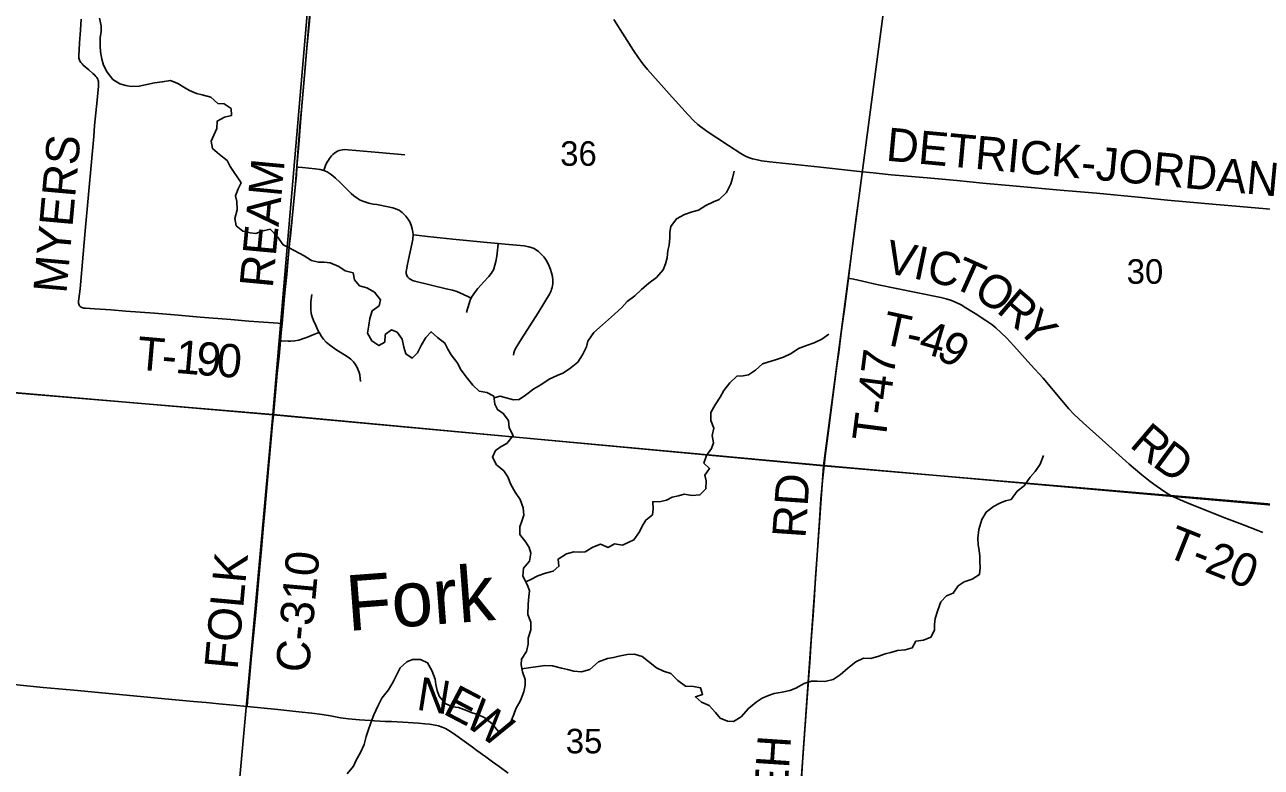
# Model space of a CAD drawing. Extents: x 0 to 1134, y 0 to 440.
# Drawn here: x 840.522 to 842.63, y 363.897 to 365.164 of the extents above; entities that cross this region are included whole.
import ezdxf

# ---------------------------------------------------------------- set-up
doc = ezdxf.new("R2010")
doc.units = 0
for name, color, linetype in [('GM_X_County_Road', 7, 'Continuous'), ('GM_X_County_Road_Text', 7, 'Continuous'), ('GM_X_Minor_River', 7, 'Continuous'), ('GM_X_Minor_River_Text', 7, 'Continuous'), ('GM_X_Section', 7, 'Continuous'), ('GM_X_Section_Text', 7, 'Continuous'), ('GM_X_Township', 7, 'Continuous'), ('GM_X_Township_Road', 7, 'Continuous'), ('GM_X_Township_Road_Text', 7, 'Continuous'), ('GM_X_Unincorporated', 7, 'Continuous')]:
    doc.layers.add(name, color=color, linetype=linetype)

msp = doc.modelspace()

# ---------------------------------------------------------------- linework, layer by layer
at = {"layer": 'GM_X_County_Road'}
for points in [[(840.9857, 364.9213), (840.9888, 364.9598), (840.9916, 364.9969), (840.9935, 365.0186), (840.9986, 365.0774), (841.0027, 365.1238), (841.0058, 365.1578), (841.0091, 365.1949), (841.0128, 365.2351), (841.0161, 365.2723), (841.0182, 365.297), (841.0212, 365.331), (841.0237, 365.3589), (841.026, 365.3867), (841.0292, 365.4207), (841.0319, 365.4485), (841.034, 365.4702), (841.0367, 365.5011), (841.0372, 365.5064)], [(841.5258, 365.1725), (841.5592, 365.1201), (841.5679, 365.1072), (841.5754, 365.0973), (841.5834, 365.0877), (841.6205, 365.0458), (841.6525, 365.01), (841.6622, 365.0001), (841.6693, 364.9936), (841.6742, 364.9896), (841.6869, 364.9806), (841.7013, 364.9711), (841.7213, 364.9578), (841.7425, 364.9442), (841.7491, 364.9404), (841.7557, 364.9375), (841.7621, 364.9351), (841.7706, 364.9331), (841.7774, 364.9317), (841.792, 364.9298), (841.8785, 364.9206), (841.9497, 364.9129)], [(840.9662, 364.7171), (840.9683, 364.7376), (840.9708, 364.7654), (840.9732, 364.7901), (840.975, 364.8086), (840.9775, 364.8333), (840.9833, 364.8919), (840.9846, 364.9073), (840.9857, 364.9213)], [(841.9497, 364.9129), (841.9681, 364.9109), (841.999, 364.908), (842.0268, 364.9053), (842.0733, 364.9014), (842.1104, 364.8982), (842.155, 364.8938), (842.2125, 364.8887), (842.2867, 364.8818), (842.3145, 364.8794), (842.3486, 364.8763), (842.4197, 364.8695), (842.4701, 364.8648), (842.5527, 364.8574), (842.5929, 364.8537), (842.6517, 364.8485), (842.7074, 364.8436), (842.7415, 364.8407), (842.7972, 364.8355), (842.8652, 364.8294), (842.9053, 364.8257), (842.9385, 364.8227)], [(840.9602, 364.6544), (840.9646, 364.7005), (840.9662, 364.7171)], [(840.9575, 364.6247), (840.9588, 364.6387), (840.9602, 364.6544)], [(840.9454, 364.4979), (840.9522, 364.5688), (840.9552, 364.5985), (840.9575, 364.6247)], [(840.9009, 364.0006), (840.9019, 364.0164), (840.9083, 364.0875), (840.9147, 364.1554), (840.917, 364.1802), (840.9201, 364.2141), (840.9256, 364.2759), (840.9282, 364.3038), (840.931, 364.3347), (840.9356, 364.3872), (840.9441, 364.483), (840.9454, 364.4979)], [(840.0509, 364.0808), (840.0706, 364.0789), (840.1015, 364.076), (840.151, 364.0715), (840.1912, 364.0679), (840.2129, 364.0661), (840.2315, 364.0647), (840.2963, 364.0592), (840.3117, 364.0578), (840.3302, 364.0559), (840.358, 364.0526), (840.392, 364.0492), (840.4259, 364.0456), (840.4507, 364.0431), (840.4971, 364.0386), (840.5527, 364.0332), (840.6053, 364.0283), (840.7785, 364.0122), (840.8094, 364.0093), (840.8311, 364.0073), (840.8527, 364.0053), (840.8777, 364.0029), (840.9009, 364.0006)], [(840.9009, 364.0006), (840.9528, 363.9953), (840.9886, 363.9918), (841.0108, 363.9893), (841.0284, 363.9868), (841.0429, 363.9845), (841.0599, 363.9816), (841.0738, 363.9798), (841.0921, 363.9779), (841.1016, 363.9771), (841.1112, 363.9765), (841.1176, 363.9761), (841.1358, 363.9753), (841.1468, 363.9748), (841.1662, 363.9739), (841.1926, 363.9722), (841.2036, 363.9713), (841.2118, 363.9703), (841.2211, 363.9689), (841.2272, 363.9675), (841.2332, 363.9655), (841.2389, 363.963), (841.2444, 363.96), (841.2523, 363.9548), (841.2748, 363.9385), (841.2848, 363.9312), (841.2924, 363.9258), (841.3075, 363.9147), (841.3192, 363.9062), (841.3302, 363.8982), (841.3458, 363.8868)]]:
    msp.add_lwpolyline(points, dxfattribs=at)
at = {"layer": 'GM_X_Minor_River'}
for points in [[(841.1046, 364.715), (841.0925, 364.7186), (841.0835, 364.7289), (841.0814, 364.7407), (841.0681, 364.7439), (841.0572, 364.7513), (841.0425, 364.7575), (841.0319, 364.7588), (841.0224, 364.7589), (841.0106, 364.7617), (840.9982, 364.7698), (840.9725, 364.7831), (840.9623, 364.7885), (840.9526, 364.8019), (840.9399, 364.815), (840.9258, 364.8114), (840.9155, 364.8077), (840.906, 364.8086), (840.8935, 364.8118), (840.8822, 364.821), (840.8797, 364.8332), (840.8837, 364.8483), (840.8831, 364.8624), (840.8806, 364.8719), (840.8857, 364.8836), (840.8904, 364.8942), (840.8717, 364.9218), (840.8665, 364.9321), (840.8537, 364.9425), (840.8417, 364.9526), (840.8396, 364.9651), (840.8439, 364.9753), (840.849, 364.9867), (840.8499, 364.9996), (840.8621, 365.0063), (840.8739, 365.0088), (840.8737, 365.0209), (840.8613, 365.0287), (840.851, 365.0296), (840.8386, 365.04), (840.8239, 365.0443), (840.8144, 365.0463), (840.8027, 365.0518), (840.7929, 365.0576), (840.7827, 365.0634), (840.7702, 365.0689), (840.7561, 365.0664), (840.7428, 365.065), (840.7295, 365.0618), (840.7165, 365.0593), (840.7032, 365.0587), (840.6938, 365.0599), (840.6839, 365.0631), (840.6715, 365.0705), (840.6621, 365.0827), (840.6558, 365.095), (840.6529, 365.1053), (840.6508, 365.1178), (840.6502, 365.1273), (840.6503, 365.1418), (840.6516, 365.152), (840.6521, 365.1622), (840.6492, 365.1748)], [(841.3218, 364.5271), (841.3321, 364.5303), (841.3423, 364.5271), (841.3548, 364.5236), (841.3643, 364.5246), (841.3755, 364.5321), (841.3893, 364.5429), (841.4015, 364.5492), (841.4157, 364.559), (841.4291, 364.5656), (841.439, 364.5693), (841.4501, 364.5768), (841.4643, 364.588), (841.4724, 364.6008), (841.4794, 364.6144), (841.4814, 364.6239), (841.4919, 364.6386), (841.5065, 364.6517), (841.5169, 364.6611), (841.5272, 364.6701), (841.5395, 364.6817), (841.5488, 364.6915), (841.5618, 364.7012), (841.5733, 364.7121), (841.5856, 364.723), (841.5987, 364.7327), (841.6098, 364.7459), (841.6138, 364.7557), (841.6166, 364.7663), (841.6182, 364.7785), (841.6202, 364.7879), (841.6212, 364.8005), (841.6213, 364.81), (841.6229, 364.8198), (841.6326, 364.8326), (841.6463, 364.84), (841.6593, 364.8445), (841.67, 364.8477), (841.6826, 364.8552), (841.6956, 364.8615), (841.7056, 364.8659), (841.7179, 364.8776), (841.7253, 364.8923), (841.7284, 364.9021), (841.7312, 364.9143)], [(841.1564, 364.0566), (841.1618, 364.0664), (841.173, 364.0766), (841.1829, 364.0806), (841.1962, 364.0808), (841.2083, 364.0754), (841.2157, 364.062), (841.2212, 364.0475), (841.2226, 364.038), (841.2248, 364.0281), (841.2281, 364.0185), (841.2382, 364.0058), (841.251, 364), (841.2612, 363.9991), (841.2745, 363.9936), (841.2843, 363.9901), (841.2941, 363.9869), (841.3062, 363.9815), (841.3186, 363.9711), (841.3287, 363.9584), (841.3413, 363.9621), (841.3498, 363.9734), (841.3553, 363.987), (841.3588, 363.9968), (841.367, 364.0108), (841.3725, 364.0255), (841.3745, 364.0369), (841.3747, 364.0468), (841.3703, 364.0598), (841.3678, 364.072), (841.3686, 364.0814), (841.3772, 364.0946), (841.38, 364.1072), (841.3801, 364.117), (841.3845, 364.1314), (841.3843, 364.1447), (841.3795, 364.1577), (841.3797, 364.1752), (841.381, 364.1885), (841.3819, 364.198), (841.3786, 364.2079), (841.3708, 364.2228), (841.3721, 364.2365), (841.3821, 364.2489), (841.3846, 364.2622), (841.3813, 364.2717), (841.3757, 364.2813), (841.3656, 364.2943), (841.3658, 364.3072), (841.3693, 364.3171), (841.3725, 364.3269), (841.3711, 364.3395), (841.366, 364.3536), (841.3578, 364.3662), (841.3504, 364.3796), (841.3452, 364.3926), (841.3385, 364.4026), (841.3257, 364.413), (841.319, 364.426), (841.3241, 364.4373), (841.3337, 364.4444), (841.3433, 364.4496), (841.3541, 364.4632), (841.3474, 364.4762), (841.3464, 364.4887), (841.3375, 364.5006), (841.3277, 364.5072), (841.3228, 364.5167), (841.3215, 364.5301), (841.3094, 364.5363), (841.2965, 364.5387), (841.2856, 364.5487), (841.274, 364.5629), (841.2647, 364.5763), (841.2599, 364.5859), (841.2483, 364.6005), (841.2431, 364.6104), (841.2379, 364.6207), (841.2251, 364.6304), (841.2142, 364.64), (841.2054, 364.6302), (841.198, 364.6178), (841.1914, 364.6042), (841.1818, 364.5948), (841.1712, 364.6025), (841.1676, 364.614), (841.1651, 364.6273), (841.1565, 364.6395), (841.1467, 364.6431), (841.1359, 364.6352), (841.1354, 364.6223), (841.125, 364.6164), (841.1134, 364.6245), (841.1059, 364.6375), (841.108, 364.6515), (841.1097, 364.6629), (841.1136, 364.6758), (841.1259, 364.6844), (841.1283, 364.6946), (841.1178, 364.7073), (841.1046, 364.715)], [(841.3757, 364.2134), (841.3844, 364.2173), (841.3966, 364.2236), (841.4096, 364.2284), (841.4226, 364.2317), (841.4322, 364.2399), (841.4308, 364.2521), (841.445, 364.2614), (841.4579, 364.2643), (841.4674, 364.2638), (841.4773, 364.2645), (841.4899, 364.2727), (841.5029, 364.2779), (841.5165, 364.272), (841.5272, 364.278), (841.5405, 364.2759), (841.5501, 364.2803), (841.56, 364.2852), (841.5697, 364.2987), (841.574, 364.3086), (841.5802, 364.3188), (841.5921, 364.3277), (841.593, 364.338), (841.5923, 364.3501), (841.606, 364.3504), (841.6155, 364.3525), (841.6255, 364.3577), (841.6362, 364.3603), (841.6457, 364.3628), (841.6597, 364.3604), (841.6726, 364.3617), (841.683, 364.3723), (841.6832, 364.3859), (841.681, 364.3955), (841.6892, 364.4068), (841.6794, 364.4156), (841.6841, 364.4289), (841.6922, 364.4406), (841.6958, 364.4504), (841.6937, 364.463), (841.6961, 364.4755), (841.6913, 364.4884), (841.6915, 364.5025), (841.6985, 364.5153), (841.707, 364.5285), (841.7132, 364.5399), (841.7237, 364.553), (841.7356, 364.5643), (841.7462, 364.5649), (841.7557, 364.5663), (841.7676, 364.5746), (841.7792, 364.5851), (841.7887, 364.588), (841.8013, 364.592), (841.8154, 364.5964), (841.8284, 364.6031), (841.841, 364.6113), (841.8544, 364.6165), (841.8677, 364.6209), (841.8807, 364.6272), (841.8926, 364.6358)], [(841.3693, 364.0647), (841.3844, 364.0672), (841.397, 364.0689), (841.4084, 364.0707), (841.4213, 364.0702), (841.4364, 364.0662), (841.4471, 364.0638), (841.4577, 364.061), (841.4705, 364.0597), (841.4847, 364.0637), (841.4996, 364.0768), (841.5149, 364.0828), (841.5252, 364.0845), (841.5347, 364.0867), (841.5484, 364.0892), (841.561, 364.0898), (841.5742, 364.0858), (841.5986, 364.0666), (841.6107, 364.0607), (841.6228, 364.0568), (841.6352, 364.0452), (841.648, 364.0352), (841.6617, 364.035), (841.6738, 364.0326), (841.6771, 364.0212), (841.6649, 364.0171), (841.6754, 364.0082), (841.6886, 364.0024), (841.6991, 363.9905), (841.707, 363.9805), (841.7198, 363.9754), (841.7297, 363.9753), (841.7431, 363.9831), (841.7554, 363.9974), (841.7685, 364.0083), (841.7788, 364.0146), (841.7895, 364.0194), (841.7994, 364.0231), (841.8127, 364.0252), (841.8257, 364.0281), (841.836, 364.0318), (841.8505, 364.04), (841.8631, 364.0437), (841.8726, 364.0439), (841.8859, 364.0434), (841.8996, 364.0466), (841.9115, 364.0549), (841.9249, 364.0661), (841.9387, 364.077), (841.9517, 364.0833), (841.9643, 364.0824), (841.9776, 364.0864), (841.9883, 364.0905), (841.9982, 364.0926), (842.0093, 364.0963), (842.0226, 364.0976), (842.0348, 364.1009), (842.041, 364.1123), (842.0536, 364.114), (842.0665, 364.1188), (842.0728, 364.1309), (842.0725, 364.1408), (842.0738, 364.1506), (842.0781, 364.165), (842.0836, 364.179), (842.0933, 364.1896), (842.1047, 364.194), (842.1132, 364.2064), (842.1232, 364.2135), (842.1369, 364.2179), (842.1492, 364.2258), (842.1505, 364.2379), (842.1498, 364.2474), (842.1496, 364.2569), (842.1486, 364.2668), (842.1468, 364.2764), (842.1465, 364.2881), (842.1479, 364.3026), (842.1534, 364.3196), (842.1604, 364.3324), (842.173, 364.3418), (842.1841, 364.3474), (842.1937, 364.3514), (842.2032, 364.354), (842.2133, 364.3679), (842.2255, 364.3773), (842.2356, 364.392), (842.2445, 364.4018), (842.2526, 364.4142), (842.2585, 364.429)], [(841.0714, 363.8858), (841.0818, 363.899), (841.0865, 363.9092), (841.0939, 363.9224), (841.1002, 363.936), (841.1034, 363.9493), (841.1069, 363.9595), (841.1124, 363.9743), (841.1167, 363.9864), (841.1234, 364.0011), (841.1304, 364.0151), (841.1416, 364.029), (841.1497, 364.043), (841.1564, 364.0566)]]:
    msp.add_lwpolyline(points, dxfattribs=at)
at = {"layer": 'GM_X_Section'}
for points in [[(840.0379, 365.5902), (841.0302, 365.5017), (840.9446, 364.4988), (839.9402, 364.5829)], [(841.0302, 365.5017), (842.0148, 365.4073), (841.8831, 364.4112), (840.9446, 364.4988)], [(842.0148, 365.4073), (842.9878, 365.3211), (842.894, 364.3251), (841.8831, 364.4112)], [(839.9402, 364.5829), (840.9446, 364.4988), (840.8539, 363.505), (839.845, 363.6002)], [(840.9446, 364.4988), (841.8831, 364.4112), (841.8128, 363.4171), (840.8539, 363.505)], [(841.8831, 364.4112), (842.894, 364.3251), (842.8073, 363.3252), (841.8128, 363.4171)]]:
    msp.add_lwpolyline(points, close=True, dxfattribs=at)
at = {"layer": 'GM_X_Township'}
msp.add_lwpolyline([(838.4147, 364.746), (839.7495, 364.6071), (839.9416, 364.5848), (840.9452, 364.4984), (841.8841, 364.4117), (842.4801, 364.359), (842.8947, 364.3223)], dxfattribs=at)
at = {"layer": 'GM_X_Township_Road'}
for points in [[(840.9602, 364.6544), (840.9539, 364.6549), (840.9038, 364.6583), (840.8729, 364.661), (840.8204, 364.6652), (840.7771, 364.6687), (840.7426, 364.6715), (840.6937, 364.6753), (840.6682, 364.6773), (840.6409, 364.6794), (840.6254, 364.6803), (840.6222, 364.6805), (840.6206, 364.6808), (840.619, 364.6812), (840.6177, 364.6819), (840.6162, 364.6829), (840.6152, 364.684), (840.6142, 364.6855), (840.6136, 364.687), (840.6133, 364.6887), (840.6131, 364.6902), (840.6132, 364.6924), (840.6135, 364.696), (840.6159, 364.7135), (840.6214, 364.7722), (840.6248, 364.8124), (840.6297, 364.868), (840.636, 364.936), (840.6391, 364.9731), (840.6407, 364.9917), (840.6426, 365.0133), (840.6448, 365.0349), (840.6468, 365.0534), (840.6472, 365.0583), (840.6473, 365.0626), (840.6474, 365.065), (840.6471, 365.0668), (840.6467, 365.0689), (840.6459, 365.0711), (840.6443, 365.0739), (840.6428, 365.0758), (840.6409, 365.0778), (840.6379, 365.0806), (840.6309, 365.0868), (840.6214, 365.0949), (840.6192, 365.0971), (840.6171, 365.0995), (840.6154, 365.1022), (840.6148, 365.1036), (840.6143, 365.1051), (840.614, 365.1067), (840.6138, 365.1083), (840.6137, 365.1114), (840.6141, 365.1208), (840.615, 365.1332), (840.6166, 365.1548), (840.6179, 365.1734)], [(841.0315, 364.9149), (841.0321, 364.9166), (841.0346, 364.9236), (841.0368, 364.9286), (841.0392, 364.933), (841.0409, 364.9356), (841.0427, 364.9381), (841.0448, 364.9404), (841.047, 364.9426), (841.0494, 364.9446), (841.0519, 364.9464), (841.0546, 364.9479), (841.0575, 364.9492), (841.0605, 364.9501), (841.0635, 364.9507), (841.0666, 364.951), (841.0728, 364.9507), (841.1255, 364.9456), (841.1694, 364.9418)], [(840.9857, 364.9213), (840.9878, 364.9211), (840.995, 364.9205), (841.0166, 364.9182), (841.0252, 364.9168), (841.0315, 364.9149)], [(841.0315, 364.9149), (841.0369, 364.9126), (841.0423, 364.9092), (841.0466, 364.906), (841.0514, 364.9023), (841.0582, 364.896), (841.0711, 364.8825), (841.0779, 364.876), (841.0828, 364.872), (841.0882, 364.8678), (841.0937, 364.8647), (841.0998, 364.8624), (841.1082, 364.8597), (841.1158, 364.858), (841.1217, 364.857), (841.1409, 364.8533), (841.1493, 364.8514), (841.1552, 364.8494), (841.16, 364.8472), (841.163, 364.8453), (841.1653, 364.8434), (841.169, 364.8396), (841.1711, 364.8374), (841.1731, 364.8351), (841.1748, 364.8326), (841.1779, 364.8273), (841.1803, 364.8217), (841.1821, 364.8158), (841.1832, 364.8098), (841.1835, 364.8068), (841.1835, 364.8053)], [(841.9259, 364.7315), (841.9302, 364.7644), (841.9393, 364.8351), (841.9459, 364.8842), (841.9482, 364.9024), (841.9494, 364.9107), (841.9497, 364.9129)], [(841.1835, 364.8053), (841.1835, 364.8037), (841.1834, 364.8007), (841.1831, 364.7977), (841.1741, 364.7551), (841.1722, 364.7459), (841.1719, 364.7427), (841.172, 364.7394), (841.1728, 364.7362), (841.1745, 364.7334), (841.1768, 364.731), (841.1796, 364.729), (841.1829, 364.7276), (841.1864, 364.7266), (841.2401, 364.7134), (841.251, 364.7108), (841.258, 364.7085), (841.2695, 364.7037), (841.2779, 364.6997), (841.2826, 364.6975)], [(841.1835, 364.8053), (841.1897, 364.8046), (841.2081, 364.8023), (841.2513, 364.7981), (841.3038, 364.7931), (841.3288, 364.7906)], [(841.2826, 364.6975), (841.2833, 364.6992), (841.2858, 364.7031), (841.2882, 364.7067), (841.294, 364.7138), (841.3044, 364.7252), (841.3128, 364.7344), (841.3167, 364.7394), (841.3183, 364.742), (841.3199, 364.7448), (841.3212, 364.7476), (841.3232, 364.7536), (841.3247, 364.7597), (841.3263, 364.7689), (841.328, 364.7842), (841.3288, 364.7906)], [(841.3288, 364.7906), (841.3408, 364.7894), (841.3599, 364.7879), (841.3728, 364.7865), (841.3809, 364.7849), (841.3868, 364.7833), (841.3899, 364.7821), (841.3926, 364.7805), (841.3954, 364.7786), (841.3975, 364.7767), (841.4022, 364.7726), (841.4044, 364.7704), (841.4064, 364.768), (841.4082, 364.7655), (841.4114, 364.7602), (841.4155, 364.7519), (841.4179, 364.7462), (841.4199, 364.7403), (841.4212, 364.7342), (841.4218, 364.7281), (841.4218, 364.725), (841.4217, 364.7219), (841.4213, 364.7188), (841.4207, 364.7158), (841.4198, 364.7128), (841.4188, 364.7099), (841.4162, 364.7042), (841.4084, 364.6909), (841.3969, 364.6725), (841.3686, 364.6279), (841.3639, 364.6205), (841.3584, 364.6115), (841.3565, 364.6072), (841.3555, 364.6041), (841.3551, 364.6001)], [(841.8844, 364.4112), (841.8862, 364.4275), (841.8923, 364.4758), (841.9029, 364.5556), (841.9069, 364.5863), (841.9093, 364.6048), (841.9124, 364.6293), (841.9152, 364.6508), (841.919, 364.6784), (841.923, 364.7091), (841.9259, 364.7315)], [(841.9259, 364.7315), (841.9279, 364.7311), (841.9349, 364.7297), (841.95, 364.7262), (841.9742, 364.7208), (842.0076, 364.7137), (842.0441, 364.7065), (842.0836, 364.6985), (842.0925, 364.6963), (842.1013, 364.6935), (842.1098, 364.6899), (842.118, 364.6857), (842.1261, 364.6811), (842.1418, 364.6713), (842.1599, 364.6594), (842.1701, 364.6523), (842.1773, 364.6465), (842.1865, 364.6383), (842.1953, 364.6297), (842.208, 364.6161), (842.237, 364.5838), (842.2576, 364.5607), (842.2894, 364.5226), (842.3017, 364.5086), (842.3103, 364.4996), (842.3262, 364.4848), (842.3586, 364.4559), (842.4046, 364.4143), (842.4258, 364.3962), (842.4404, 364.3846), (842.4504, 364.3772), (842.4654, 364.3669), (842.4718, 364.3628), (842.4756, 364.3607), (842.4803, 364.3584)], [(841.0235, 364.6388), (841.0215, 364.6426), (841.0176, 364.6506), (841.0136, 364.659), (841.0114, 364.6654), (841.0099, 364.6713), (841.0093, 364.6779), (841.0091, 364.6843), (841.0096, 364.6909), (841.0111, 364.7034)], [(841.2745, 364.6727), (841.2765, 364.6789), (841.2799, 364.6902), (841.2817, 364.6956), (841.2826, 364.6975)], [(840.9575, 364.6247), (840.9598, 364.6246), (840.9704, 364.624), (840.9753, 364.6238), (840.9817, 364.6243), (840.9888, 364.6258), (840.9953, 364.6278), (841.0039, 364.631), (841.0118, 364.6342), (841.0203, 364.6375), (841.0235, 364.6388)], [(841.0938, 364.5552), (841.0937, 364.5603), (841.093, 364.5665), (841.092, 364.5704), (841.0897, 364.5761), (841.0883, 364.5788), (841.0868, 364.582), (841.0851, 364.5846), (841.082, 364.5885), (841.0776, 364.593), (841.0729, 364.5965), (841.0668, 364.6005), (841.0537, 364.6088), (841.0459, 364.6142), (841.0409, 364.618), (841.0356, 364.6224), (841.0311, 364.6273), (841.0275, 364.6322), (841.0245, 364.637), (841.0235, 364.6388)], [(841.8451, 363.868), (841.8476, 363.9053), (841.8504, 363.9456), (841.8538, 363.9921), (841.8583, 364.0541), (841.8599, 364.0758), (841.8625, 364.113), (841.8656, 364.1564), (841.8678, 364.1905), (841.8698, 364.2215), (841.8724, 364.2587), (841.8747, 364.2928), (841.8764, 364.3177), (841.879, 364.3549), (841.8816, 364.3858), (841.8844, 364.4112)], [(842.4803, 364.3584), (842.4842, 364.3566), (842.4912, 364.3535), (842.5052, 364.3476), (842.5658, 364.3234), (842.5977, 364.3111), (842.6238, 364.3011), (842.6322, 364.2974)]]:
    msp.add_lwpolyline(points, dxfattribs=at)
at = {"layer": 'GM_X_Unincorporated'}
for points in [[(839.9416, 364.5848), (840.9452, 364.4984), (840.952, 364.5693), (840.955, 364.599), (840.9573, 364.6253), (840.9585, 364.6392), (840.96, 364.655), (840.9644, 364.7011), (840.968, 364.7381), (840.9706, 364.7659), (840.973, 364.7906), (840.9748, 364.8091), (840.9773, 364.8338), (840.9831, 364.8924), (840.9844, 364.9078), (840.9855, 364.9218), (840.9885, 364.9604), (840.9914, 364.9975), (840.9932, 365.0191), (840.9983, 365.0779), (841.0025, 365.1243), (841.0056, 365.1583), (841.0089, 365.1955)], [(841.0089, 365.1955), (841.0056, 365.1583), (841.0025, 365.1243), (840.9983, 365.0779), (840.9932, 365.0191), (840.9914, 364.9975), (840.9885, 364.9604), (840.9855, 364.9218), (840.9844, 364.9078), (840.9831, 364.8924), (840.9773, 364.8338), (840.9748, 364.8091), (840.973, 364.7906), (840.9706, 364.7659), (840.968, 364.7381), (840.9644, 364.7011), (840.96, 364.655), (840.9585, 364.6392), (840.9573, 364.6253), (840.955, 364.599), (840.952, 364.5693), (840.9452, 364.4984), (841.8841, 364.4117), (842.4801, 364.359), (842.8947, 364.3223)]]:
    msp.add_lwpolyline(points, dxfattribs=at)

# ---------------------------------------------------------------- texts
at = {"layer": 'GM_X_County_Road_Text'}
for s, height, rotation, p in [('DETRICK-JORDAN', 0.056818, 354.7624, (841.9887, 364.9321)), ('REAM', 0.05682, 84.5891, (840.9443, 364.7135)), ('FOLK', 0.05682, 84.782, (840.8843, 364.0626)), ('C-310', 0.05682, 84.7823, (841.0057, 364.057)), ('N', 0.0568, 351.0791, (841.1878, 363.9955)), ('E', 0.0568, 332.3463, (841.2325, 363.9893)), ('W', 0.0568, 324.1832, (841.2683, 363.9707))]:
    msp.add_text(s, height=height, rotation=rotation, dxfattribs=at).set_placement(p)
at = {"layer": 'GM_X_Minor_River_Text'}
msp.add_text('Fork', height=0.0947, rotation=4.283, dxfattribs=at).set_placement((841.0728, 364.1294))
at = {"layer": 'GM_X_Section_Text'}
for s, p in [('36', (841.4345, 364.9232)), ('30', (842.4003, 364.7219)), ('35', (841.444, 363.9207))]:
    msp.add_text(s, height=0.04186, rotation=0, dxfattribs=at).set_placement(p)
at = {"layer": 'GM_X_Township_Road_Text'}
for s, height, rotation, p in [('MYERS', 0.05682, 84.8567, (840.5926, 364.7043)), ('V', 0.0568, 348.1978, (841.9853, 364.7417)), ('I', 0.0568, 348.168, (842.0342, 364.7315)), ('C', 0.0568, 347.2011, (842.0568, 364.7267)), ('T', 0.0568, 335.8965, (842.0995, 364.7173)), ('O', 0.0568, 326.5403, (842.1361, 364.7011)), ('R', 0.0568, 319.5778, (842.1764, 364.6747)), ('T', 0.0568, 347.6781, (841.9797, 364.6201)), ('Y', 0.0568, 313.1064, (842.2107, 364.6456)), ('4', 0.0568, 343.5435, (842.0429, 364.6063)), ('T', 0.0568, 355.031, (840.7113, 364.5757)), ('-', 0.0568, 347.6016, (842.0212, 364.611)), ('9', 0.0568, 327.8573, (842.0728, 364.5981)), ('1', 0.0568, 355.0643, (840.777, 364.57)), ('9', 0.0568, 355.1929, (840.812, 364.567)), ('0', 0.0568, 355.7912, (840.8475, 364.564)), ('T-47', 0.05682, 82.6601, (841.9885, 364.4506)), ('-', 0.0568, 355.0394, (840.7537, 364.572)), ('R', 0.0568, 319.5088, (842.4034, 364.4453)), ('D', 0.0568, 323.5953, (842.4423, 364.4123)), ('RD', 0.05682, 86.0508, (841.8525, 364.2868)), ('T-20', 0.05682, 338.2081, (842.4643, 364.2581)), ('TECUMSEH', 0.05682, 86.211, (841.8, 363.5236))]:
    msp.add_text(s, height=height, rotation=rotation, dxfattribs=at).set_placement(p)

doc.saveas('drawing.dxf')
